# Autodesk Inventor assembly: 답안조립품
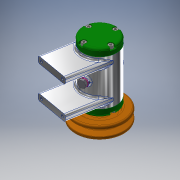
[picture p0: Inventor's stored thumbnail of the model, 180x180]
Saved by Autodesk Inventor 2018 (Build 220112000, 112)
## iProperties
Created: 2020-07
Part Number: 답안조립품
Material: 일반
Document SubType Name: Assembly
Designer: home
Author: home
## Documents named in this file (14)
- C:\Users\home\Desktop\700706V1028\답안조립품.iam
- C:\Users\home\Desktop\700706V1028\본체.ipt
- C:\Users\home\Desktop\700706V1028\베어링 6002.ipt
- C:\Users\home\Desktop\700706V1028\뒤커버.ipt
- C:\Users\home\Desktop\700706V1028\앞커버.ipt
- C:\Users\home\Desktop\700706V1028\축.ipt
- C:\Users\home\Desktop\700706V1028\볼트 M4x12.ipt
- C:\Users\home\Desktop\700706V1028\키 3x3x12.ipt
- C:\Users\home\Desktop\700706V1028\V벨트풀리.ipt
- C:\Users\home\Desktop\700706V1028\와셔 8x17.ipt
- C:\Users\home\Desktop\700706V1028\스프링와셔 8.ipt
- C:\Users\home\Desktop\700706V1028\와셔 6x11.5.ipt
- C:\Users\home\Desktop\700706V1028\너트 M8.ipt
- C:\Users\home\Desktop\700706V1028\볼트 M6x8.ipt
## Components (1 placed, 1 different names)
1. V벨트풀리:1
